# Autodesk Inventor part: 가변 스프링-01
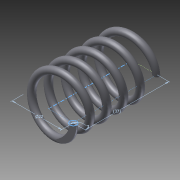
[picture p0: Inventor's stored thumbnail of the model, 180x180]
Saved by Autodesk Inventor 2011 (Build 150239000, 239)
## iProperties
Created: 2015-05
Part Number: 가변 스프링-01
Document SubType Name: Modeling
Designer: Administrator
Density: 7.87 g/cm^3
Material: 탄소강
Mass: 18.8475 g
Surface Area: 32.4803 cm^2
Volume: 2.39485 cm^3
Author: Administrator
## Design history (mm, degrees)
sketch "스케치1"
  geometry: L1 (0, 0)-(11, 0); L2 (11, 0)-(11, 25.358); L3 (11, 25.358)-(0, 25.358); L4 (0, 25.358)-(0, 0); C1 r 1.5 at (11, 0)
  constraints: 8 end point, 2 parallel, 1 centre point, 1 coincident, 1 horizontal, 1 perpendicular
  dimensions: "d0" = 3 diameter of C1; "d1" = 22 diameter of L2 L4; "d2" = 25.35829 distance of L1.end L2.end (derived)
feature "코일1" sketch "스케치1" pitch "d3" = 10; turns "d5" = 5; dims "d4" = 25.35829 (= d2), "d6" = 0, angle "d7" = 90 deg, angle "d8" = 90 deg, "d9" = 0, "d10" = 0
node "작업 평면1"
sketch "스케치2"
  geometry: L1 (0, 0)-(3, 0) reference; 1 further point
  constraints: 1 horizontal alignment
extrude "돌출1" cut sketch "스케치2" distance "d11" = 10; taper "d12" = 0 deg
node "작업 평면2"
sketch "스케치3"
  geometry: L1 (3, 0)-(0, 0) reference; 1 further point
  constraints: 1 horizontal alignment
extrude "돌출2" cut sketch "스케치3" stored distance "d13" = 10; taper "d14" = 0 deg
node "솔리드1"
node "절단 모서리 투영1"
node "절단 모서리 투영2"
